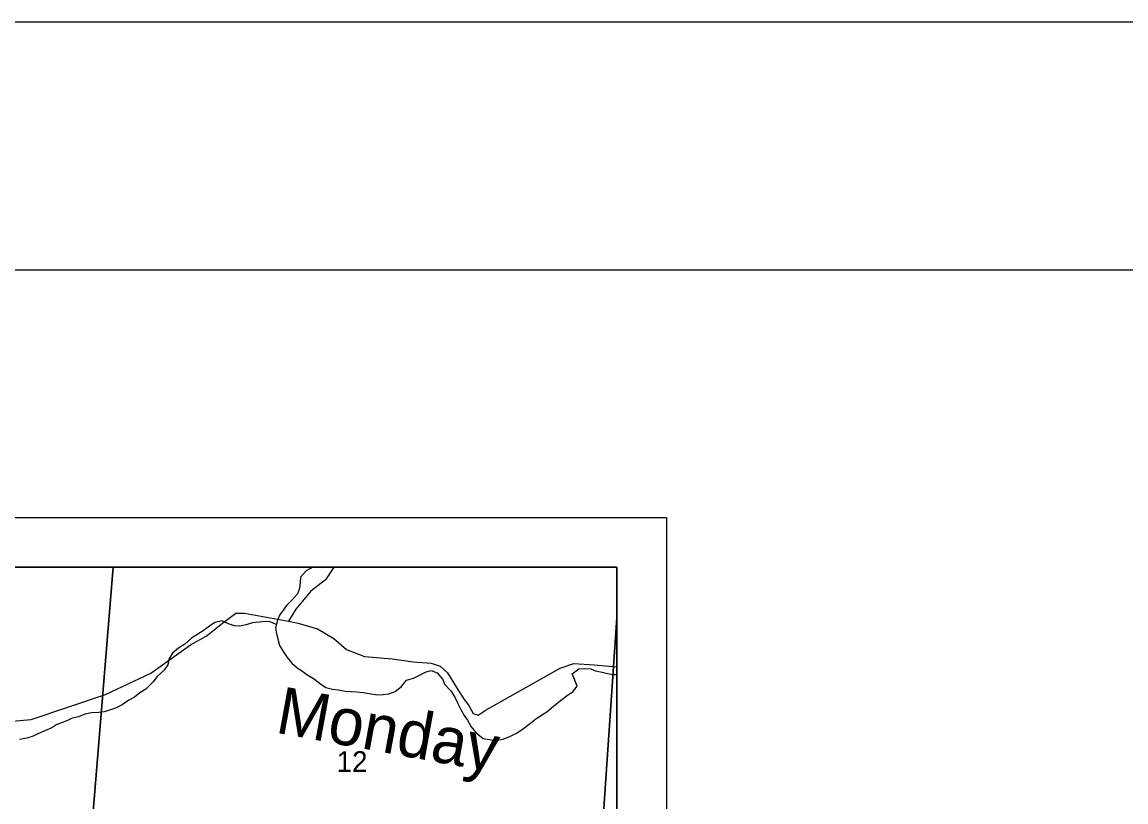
# Model space of a CAD drawing. Extents: x 39.8 to 73.8, y 13 to 35.
# Drawn here: x 47.463 to 49.69, y 33.391 to 34.965 of the extents above; entities that cross this region are included whole.
import ezdxf

# ---------------------------------------------------------------- set-up
doc = ezdxf.new("R2010")
doc.units = 0
for name, color, linetype in [('GM_X_Corporation', 7, 'Continuous'), ('GM_X_County_Road', 7, 'Continuous'), ('GM_X_Minor_River', 7, 'Continuous'), ('GM_X_Minor_River_Text', 7, 'Continuous'), ('GM_X_Section_Text', 7, 'Continuous'), ('GM_X_Township_Road', 7, 'Continuous'), ('SH_Border', 7, 'Continuous'), ('SH_Cut_Line', 7, 'Continuous'), ('SH_Data', 7, 'Continuous')]:
    doc.layers.add(name, color=color, linetype=linetype)

msp = doc.modelspace()

# ---------------------------------------------------------------- linework, layer by layer
at = {"layer": 'GM_X_Corporation'}
msp.add_lwpolyline([(47.095, 27.8783), (47.5149, 27.8498), (47.5414, 27.8484), (48.663, 27.7809), (48.663, 33.865), (43.6158, 33.865)], dxfattribs=at)
for points in [[(47.647, 33.865), (46.6307, 33.865), (46.5718, 33.0824), (47.5774, 33.0099)], [(48.663, 33.7628), (48.663, 33.865), (47.647, 33.865), (47.5774, 33.0099), (48.6073, 32.9443)], [(48.663, 32.941), (48.663, 33.7628), (48.6073, 32.9443)]]:
    msp.add_lwpolyline(points, close=True, dxfattribs=at)
at = {"layer": 'GM_X_County_Road'}
msp.add_lwpolyline([(48.0918, 33.865), (48.0756, 33.839), (48.0459, 33.8166), (48.0157, 33.7804), (48.001, 33.7561), (48.0203, 33.752), (48.0591, 33.7404), (48.0921, 33.721), (48.1178, 33.6989), (48.1541, 33.6846), (48.2095, 33.6796), (48.2521, 33.6741), (48.2882, 33.6711), (48.3069, 33.6653), (48.3212, 33.6514), (48.3394, 33.6217), (48.3549, 33.5979), (48.3646, 33.5855), (48.3693, 33.5768), (48.3732, 33.5693), (48.3831, 33.5664), (48.3996, 33.5772), (48.5487, 33.6612), (48.5759, 33.6703), (48.617, 33.6674), (48.663, 33.664)], dxfattribs=at)
at = {"layer": 'GM_X_Minor_River'}
for p, q in [((47.8519, 33.7531), (47.8414, 33.7459)), ((47.8663, 33.7562), (47.8519, 33.7531)), ((47.8796, 33.7502), (47.8663, 33.7562)), ((47.9413, 33.7538), (47.9281, 33.7522)), ((47.9538, 33.7553), (47.9413, 33.7538)), ((47.9636, 33.7546), (47.9538, 33.7553)), ((47.9761, 33.7492), (47.9636, 33.7546)), ((47.8285, 33.7363), (47.8176, 33.7295)), ((47.8414, 33.7459), (47.8285, 33.7363)), ((47.8921, 33.7464), (47.8796, 33.7502)), ((47.9016, 33.7457), (47.8921, 33.7464)), ((47.9156, 33.7487), (47.9016, 33.7457)), ((47.9281, 33.7522), (47.9156, 33.7487)), ((47.7915, 33.7097), (47.7791, 33.7013)), ((47.8047, 33.7218), (47.7915, 33.7097)), ((47.8176, 33.7295), (47.8047, 33.7218)), ((47.7666, 33.691), (47.7591, 33.6792)), ((47.7791, 33.7013), (47.7666, 33.691)), ((47.7576, 33.6674), (47.7501, 33.6572)), ((47.7591, 33.6792), (47.7576, 33.6674)), ((47.7354, 33.6435), (47.7275, 33.6332)), ((47.7501, 33.6572), (47.7354, 33.6435)), ((47.7275, 33.6332), (47.7132, 33.6184)), ((47.6901, 33.6027), (47.6788, 33.5966)), ((47.7007, 33.6111), (47.6901, 33.6027)), ((47.7132, 33.6184), (47.7007, 33.6111)), ((47.6395, 33.576), (47.6289, 33.5726)), ((47.652, 33.5802), (47.6395, 33.576)), ((47.6652, 33.5871), (47.652, 33.5802)), ((47.6788, 33.5966), (47.6652, 33.5871)), ((47.5548, 33.5557), (47.5431, 33.5507)), ((47.5646, 33.5599), (47.5548, 33.5557)), ((47.5771, 33.5629), (47.5646, 33.5599)), ((47.5899, 33.5679), (47.5771, 33.5629)), ((47.6036, 33.571), (47.5899, 33.5679)), ((47.6179, 33.5714), (47.6036, 33.571)), ((47.6289, 33.5726), (47.6179, 33.5714)), ((47.5106, 33.535), (47.4954, 33.5282)), ((47.5234, 33.5408), (47.5106, 33.535)), ((47.5332, 33.5476), (47.5234, 33.5408)), ((47.5431, 33.5507), (47.5332, 33.5476)), ((47.4728, 33.5194), (47.458, 33.517)), ((47.4856, 33.524), (47.4728, 33.5194)), ((47.4954, 33.5282), (47.4856, 33.524))]:
    msp.add_line(p, q, dxfattribs=at)
for points in [[(48.0502, 33.865), (48.0499, 33.8649), (48.0363, 33.8576), (48.0246, 33.8447), (48.0239, 33.8348), (48.0232, 33.8219), (48.0191, 33.8113), (48.0085, 33.7999), (47.9968, 33.7877), (47.9897, 33.7782), (47.9825, 33.7679), (47.9784, 33.7573), (47.9743, 33.7425), (47.9762, 33.7311), (47.9793, 33.7194), (47.9828, 33.7069), (47.9896, 33.6944), (47.998, 33.6822), (48.0083, 33.6701), (48.0201, 33.6603), (48.0296, 33.6543), (48.0398, 33.6467), (48.0527, 33.6392), (48.063, 33.6305), (48.0763, 33.6218), (48.0896, 33.6188), (48.1009, 33.6173), (48.1149, 33.6147), (48.1256, 33.6136), (48.1388, 33.6133), (48.1513, 33.6122), (48.1631, 33.6099)], [(48.1631, 33.6099), (48.1801, 33.607), (48.1918, 33.6077), (48.2032, 33.6089), (48.2157, 33.6139), (48.2289, 33.6242), (48.2387, 33.6367), (48.2527, 33.6406), (48.2651, 33.6471), (48.2784, 33.6539), (48.2882, 33.6562), (48.3007, 33.6517), (48.3118, 33.6381), (48.3156, 33.6286), (48.3278, 33.615), (48.3361, 33.6025), (48.3419, 33.59), (48.3491, 33.5764), (48.3549, 33.5658), (48.3617, 33.5559), (48.3693, 33.5427), (48.3792, 33.5306), (48.3933, 33.5189), (48.4183, 33.5151), (48.4338, 33.5179), (48.4486, 33.5236), (48.4607, 33.5297), (48.472, 33.5369), (48.4859, 33.548), (48.4995, 33.559), (48.5112, 33.5663), (48.5218, 33.5731), (48.535, 33.5842), (48.5486, 33.5952), (48.5633, 33.6063), (48.5739, 33.6135), (48.5826, 33.6249), (48.578, 33.637), (48.5726, 33.6495), (48.5862, 33.6594), (48.5983, 33.6602), (48.6104, 33.6595), (48.6199, 33.6558), (48.6332, 33.6528), (48.6438, 33.6505), (48.6555, 33.6479), (48.663, 33.6482)]]:
    msp.add_lwpolyline(points, dxfattribs=at)
at = {"layer": 'GM_X_Township_Road'}
msp.add_lwpolyline([(47.1239, 33.865), (47.1227, 33.7864), (47.1297, 33.7652), (47.2207, 33.6366), (47.2553, 33.5878), (47.3505, 33.5496), (47.4283, 33.5524), (47.4814, 33.5573), (47.6313, 33.6077), (47.7232, 33.6509), (47.8029, 33.7084), (47.8346, 33.7257), (47.8678, 33.7518), (47.8942, 33.7717), (47.9117, 33.7719), (48.001, 33.7561)], dxfattribs=at)
at = {"layer": 'SH_Border'}
msp.add_lwpolyline([(41.263, 34.465), (73.263, 34.465), (73.263, 13.465), (41.263, 13.465)], close=True, dxfattribs=at)
at = {"layer": 'SH_Cut_Line'}
msp.add_lwpolyline([(39.763, 12.965), (73.763, 12.965), (73.763, 34.965), (39.763, 34.965)], close=True, dxfattribs=at)
at = {"layer": 'SH_Data'}
for p, q in [((41.763, 33.965), (48.763, 33.965)), ((48.763, 33.965), (48.763, 26.965)), ((41.863, 33.865), (48.663, 33.865)), ((48.663, 33.865), (48.663, 27.065))]:
    msp.add_line(p, q, dxfattribs=at)

# ---------------------------------------------------------------- texts
at = {"layer": 'GM_X_Minor_River_Text'}
msp.add_text('Monday', height=0.0947, rotation=349.6421, dxfattribs=at).set_placement((47.9721, 33.5313))
at = {"layer": 'GM_X_Section_Text'}
msp.add_text('12', height=0.04186, rotation=0, dxfattribs=at).set_placement((48.0978, 33.4515))

doc.saveas('drawing.dxf')
